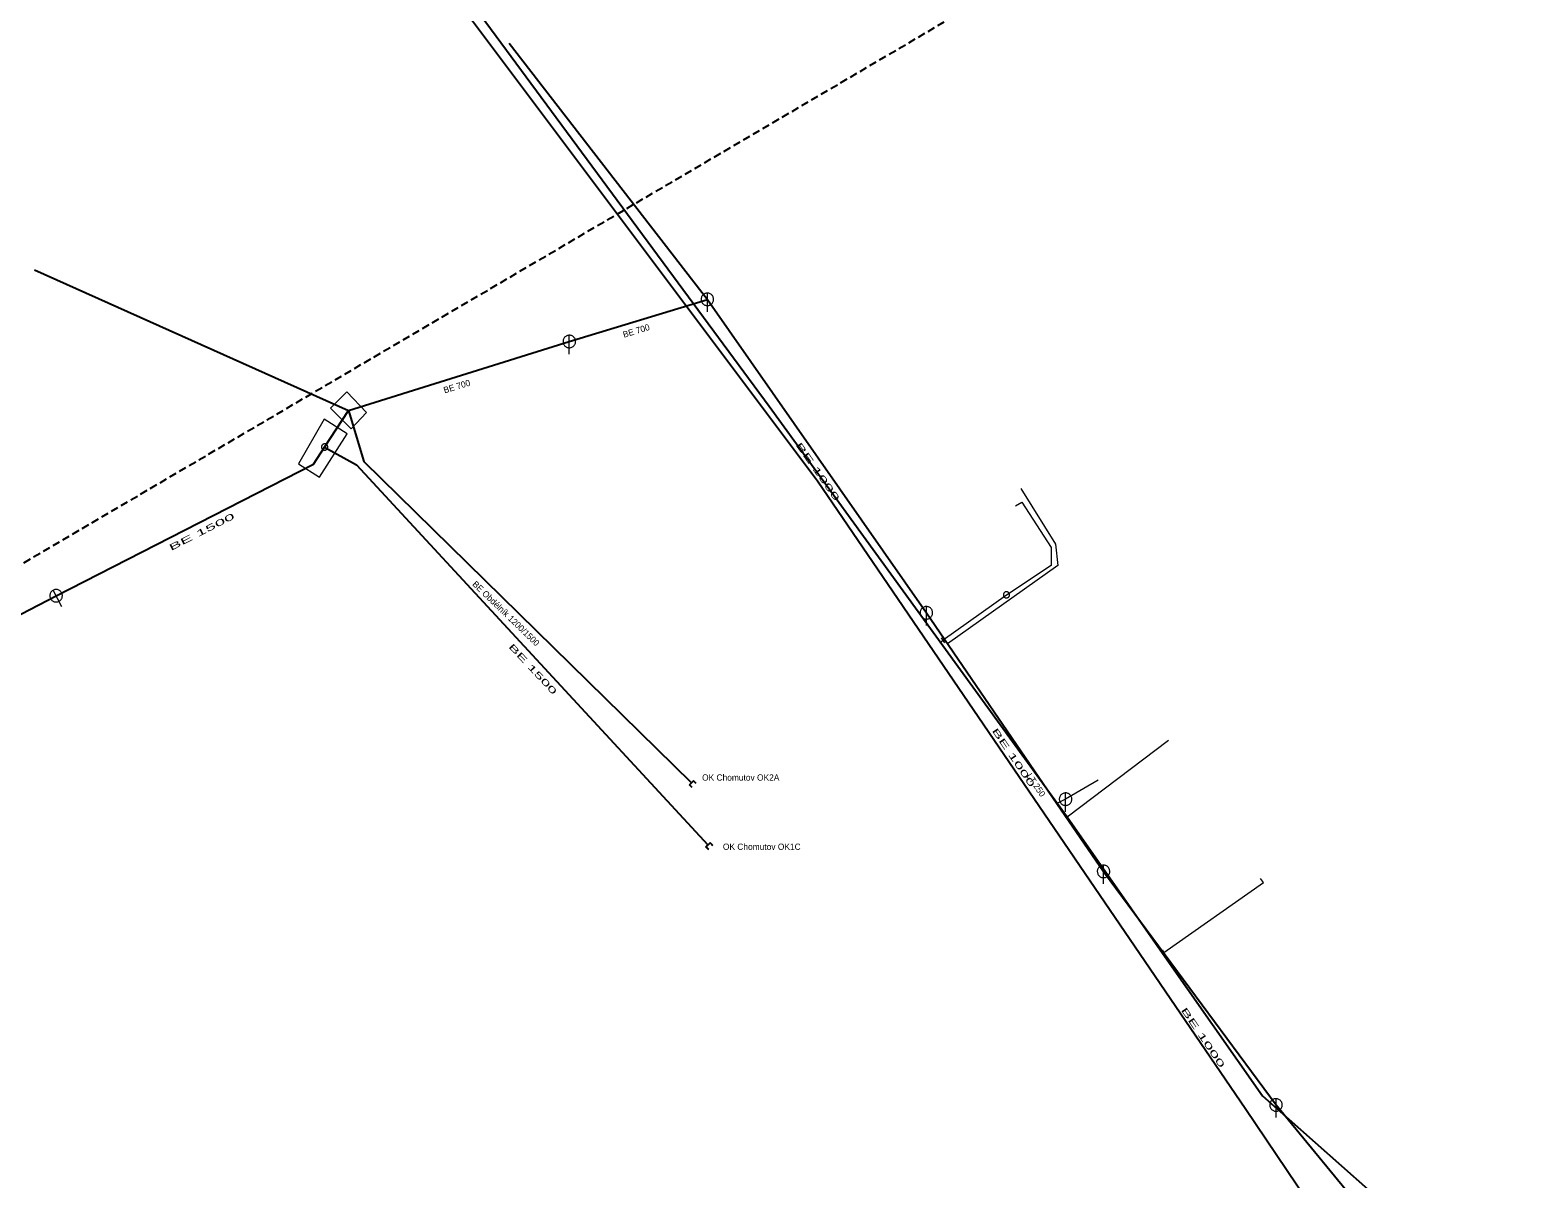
# Model space of a CAD drawing. Extents: x -807203 to -805207, y -993656 to -992505.
# Drawn here: x -806744.2 to -806503.5, y -992783.3 to -992600 of the extents above; entities that cross this region are included whole.
import ezdxf

# ---------------------------------------------------------------- set-up
doc = ezdxf.new("R2010")
doc.units = 0
doc.header["$LTSCALE"] = 0.4
doc.linetypes.add('MEDIUM_DASHED', pattern=[4.5, 3, -1.5])
for name, color, linetype, lineweight in [('1', 7, 'Continuous', 13), ('11', 7, 'Continuous', 13), ('13', 7, 'Continuous', 13), ('14', 7, 'Continuous', 25), ('17', 7, 'Continuous', 25), ('22', 7, 'Continuous', 13), ('23', 7, 'Continuous', 13), ('29', 7, 'Continuous', 13), ('31', 7, 'Continuous', 13), ('34', 7, 'Continuous', 13), ('63', 7, 'MEDIUM_DASHED', 25)]:
    doc.layers.add(name, color=color, linetype=linetype, lineweight=lineweight)

msp = doc.modelspace()

# ---------------------------------------------------------------- linework, layer by layer
at = {"layer": '1'}
for points in [[(-806693.63, -992657.714), (-806696.28, -992660.291), (-806692.966, -992663.625), (-806690.539, -992660.993)], [(-806697.274, -992662.058), (-806701.357, -992669.204), (-806698.039, -992671.347), (-806693.599, -992664.406)]]:
    msp.add_lwpolyline(points, close=True, dxfattribs=at)
at = {"layer": '11'}
for p, q in [((-806573.713, -992719.711), (-806578.93, -992722.73)), ((-806578.93, -992722.73), (-806580.31, -992723.399))]:
    msp.add_line(p, q, dxfattribs=at)
msp.add_lwpolyline([(-806586.063, -992673.109), (-806580.563, -992682.012), (-806580.166, -992685.451), (-806597.76, -992697.928)], dxfattribs=at)
at = {"layer": '13'}
for p, q in [((-806588.368, -992690.147), (-806598.47, -992697.356)), ((-806598.914, -992697.673), (-806598.47, -992697.356)), ((-806578.693, -992725.553), (-806562.513, -992713.331))]:
    msp.add_line(p, q, dxfattribs=at)
for points in [[(-806586.913, -992675.926), (-806585.921, -992675.331), (-806581.224, -992682.541), (-806581.224, -992685.451), (-806588.368, -992690.147)], [(-806563.258, -992747.217), (-806547.336, -992736.038), (-806547.826, -992735.393)]]:
    msp.add_lwpolyline(points, dxfattribs=at)
at = {"layer": '14'}
for p, q in [((-806667.734, -992602.07), (-806636.101, -992642.942)), ((-806743.532, -992638.21), (-806693.41, -992660.67)), ((-806636.101, -992642.942), (-806601.151, -992692.978)), ((-806572.87, -992734.26), (-806545.34, -992771.539)), ((-806545.34, -992771.539), (-806510.489, -992813.739))]:
    msp.add_line(p, q, dxfattribs=at)
at = {"layer": '14', "lineweight": 13}
msp.add_line((-806563.455, -992747.297), (-806563.258, -992747.217), dxfattribs=at)
at = {"layer": '14'}
for points in [[(-806693.41, -992660.67), (-806658.14, -992649.67), (-806636.101, -992642.942)], [(-806784.8, -992713.495), (-806740.059, -992690.25), (-806698.98, -992669.26), (-806697.199, -992666.514), (-806693.41, -992660.67)], [(-806693.41, -992660.67), (-806690.953, -992668.827), (-806638.67, -992720.07)], [(-806697.199, -992666.514), (-806692.136, -992669.339), (-806636.03, -992730)], [(-806601.151, -992692.978), (-806580.31, -992723.399), (-806572.87, -992734.26)]]:
    msp.add_lwpolyline(points, dxfattribs=at)
at = {"layer": '17'}
for points in [[(-806778.418, -992505.129), (-806735.947, -992534.177), (-806710.556, -992555.706), (-806685.234, -992582.874), (-806618.534, -992671.901), (-806550.144, -992772.21), (-806538.741, -992789.206), (-806527.647, -992801.493), (-806521.969, -992806.479)], [(-806713.738, -992548.818), (-806700.103, -992562.285), (-806693.842, -992569.743), (-806679.548, -992587.69), (-806626.239, -992660.002), (-806578.693, -992725.552), (-806563.455, -992747.297), (-806547.484, -992770.088), (-806530.704, -992784.989), (-806525.097, -992790.538), (-806497.604, -992819.259), (-806477.405, -992839.403), (-806476.543, -992840.262)]]:
    msp.add_lwpolyline(points, dxfattribs=at)
at = {"layer": '22'}
for p, q in [((-806636.101, -992644.942), (-806636.1, -992641.942)), ((-806658.14, -992651.67), (-806658.139, -992648.67)), ((-806739.143, -992692.028), (-806740.516, -992689.361)), ((-806601.151, -992694.978), (-806601.15, -992691.978)), ((-806578.93, -992724.73), (-806578.929, -992721.73)), ((-806572.87, -992736.26), (-806572.869, -992733.26)), ((-806545.34, -992773.539), (-806545.339, -992770.539))]:
    msp.add_line(p, q, dxfattribs=at)
for points in [[(-806635.101, -992642.942), (-806635.106, -992642.833), (-806635.124, -992642.725), (-806635.154, -992642.619), (-806635.194, -992642.518), (-806635.246, -992642.421), (-806635.308, -992642.331), (-806635.38, -992642.248), (-806635.46, -992642.174), (-806635.548, -992642.108), (-806635.642, -992642.053), (-806635.742, -992642.008), (-806635.847, -992641.975), (-806635.954, -992641.953), (-806636.063, -992641.943), (-806636.173, -992641.945), (-806636.281, -992641.959), (-806636.388, -992641.984), (-806636.491, -992642.021), (-806636.589, -992642.07), (-806636.681, -992642.128), (-806636.767, -992642.197), (-806636.844, -992642.274), (-806636.913, -992642.36), (-806636.972, -992642.452), (-806637.02, -992642.55), (-806637.057, -992642.653), (-806637.083, -992642.76), (-806637.097, -992642.868), (-806637.1, -992642.978), (-806637.09, -992643.087), (-806637.069, -992643.194), (-806637.035, -992643.298), (-806636.991, -992643.398), (-806636.936, -992643.493), (-806636.87, -992643.581), (-806636.796, -992643.661), (-806636.713, -992643.733), (-806636.623, -992643.795), (-806636.527, -992643.847), (-806636.425, -992643.888), (-806636.32, -992643.918), (-806636.212, -992643.936), (-806636.102, -992643.942), (-806635.993, -992643.936), (-806635.885, -992643.918), (-806635.78, -992643.889), (-806635.678, -992643.848), (-806635.581, -992643.796), (-806635.491, -992643.734), (-806635.408, -992643.663), (-806635.333, -992643.583), (-806635.268, -992643.495), (-806635.212, -992643.401), (-806635.168, -992643.301), (-806635.134, -992643.197), (-806635.112, -992643.089), (-806635.102, -992642.98)], [(-806657.14, -992649.67), (-806657.145, -992649.561), (-806657.163, -992649.453), (-806657.193, -992649.347), (-806657.233, -992649.246), (-806657.285, -992649.149), (-806657.347, -992649.059), (-806657.419, -992648.976), (-806657.499, -992648.902), (-806657.587, -992648.836), (-806657.681, -992648.781), (-806657.781, -992648.736), (-806657.886, -992648.703), (-806657.993, -992648.681), (-806658.102, -992648.671), (-806658.212, -992648.673), (-806658.32, -992648.687), (-806658.427, -992648.712), (-806658.53, -992648.749), (-806658.628, -992648.798), (-806658.72, -992648.856), (-806658.806, -992648.925), (-806658.883, -992649.002), (-806658.952, -992649.088), (-806659.011, -992649.18), (-806659.059, -992649.278), (-806659.096, -992649.381), (-806659.122, -992649.488), (-806659.136, -992649.596), (-806659.139, -992649.706), (-806659.129, -992649.815), (-806659.108, -992649.922), (-806659.074, -992650.026), (-806659.03, -992650.126), (-806658.975, -992650.221), (-806658.909, -992650.309), (-806658.835, -992650.389), (-806658.752, -992650.461), (-806658.662, -992650.523), (-806658.566, -992650.575), (-806658.464, -992650.616), (-806658.359, -992650.646), (-806658.251, -992650.664), (-806658.141, -992650.67), (-806658.032, -992650.664), (-806657.924, -992650.646), (-806657.819, -992650.617), (-806657.717, -992650.576), (-806657.62, -992650.524), (-806657.53, -992650.462), (-806657.447, -992650.391), (-806657.372, -992650.311), (-806657.307, -992650.223), (-806657.251, -992650.129), (-806657.207, -992650.029), (-806657.173, -992649.925), (-806657.151, -992649.817), (-806657.141, -992649.708)], [(-806739.169, -992689.792), (-806739.224, -992689.698), (-806739.29, -992689.61), (-806739.365, -992689.53), (-806739.447, -992689.458), (-806739.538, -992689.396), (-806739.634, -992689.344), (-806739.736, -992689.303), (-806739.841, -992689.274), (-806739.949, -992689.256), (-806740.058, -992689.25), (-806740.168, -992689.256), (-806740.276, -992689.274), (-806740.381, -992689.304), (-806740.483, -992689.345), (-806740.58, -992689.397), (-806740.669, -992689.459), (-806740.753, -992689.53), (-806740.828, -992689.61), (-806740.892, -992689.699), (-806740.947, -992689.792), (-806740.992, -992689.893), (-806741.026, -992689.997), (-806741.048, -992690.105), (-806741.058, -992690.214), (-806741.056, -992690.323), (-806741.041, -992690.431), (-806741.016, -992690.538), (-806740.979, -992690.641), (-806740.93, -992690.739), (-806740.871, -992690.832), (-806740.803, -992690.917), (-806740.726, -992690.994), (-806740.641, -992691.063), (-806740.548, -992691.122), (-806740.449, -992691.17), (-806740.347, -992691.207), (-806740.24, -992691.233), (-806740.132, -992691.247), (-806740.023, -992691.25), (-806739.913, -992691.239), (-806739.806, -992691.218), (-806739.702, -992691.184), (-806739.601, -992691.139), (-806739.507, -992691.084), (-806739.419, -992691.019), (-806739.339, -992690.945), (-806739.267, -992690.862), (-806739.205, -992690.771), (-806739.153, -992690.675), (-806739.112, -992690.574), (-806739.082, -992690.468), (-806739.065, -992690.36), (-806739.058, -992690.251), (-806739.064, -992690.142), (-806739.082, -992690.034), (-806739.112, -992689.928), (-806739.153, -992689.826)], [(-806600.151, -992692.978), (-806600.156, -992692.869), (-806600.174, -992692.761), (-806600.204, -992692.655), (-806600.244, -992692.554), (-806600.296, -992692.457), (-806600.358, -992692.367), (-806600.43, -992692.284), (-806600.51, -992692.21), (-806600.598, -992692.144), (-806600.692, -992692.089), (-806600.792, -992692.044), (-806600.897, -992692.011), (-806601.004, -992691.989), (-806601.113, -992691.979), (-806601.223, -992691.981), (-806601.331, -992691.995), (-806601.438, -992692.02), (-806601.541, -992692.057), (-806601.639, -992692.106), (-806601.731, -992692.164), (-806601.817, -992692.233), (-806601.894, -992692.31), (-806601.963, -992692.396), (-806602.022, -992692.488), (-806602.07, -992692.586), (-806602.107, -992692.689), (-806602.133, -992692.796), (-806602.147, -992692.904), (-806602.15, -992693.014), (-806602.14, -992693.123), (-806602.119, -992693.23), (-806602.085, -992693.334), (-806602.041, -992693.434), (-806601.986, -992693.529), (-806601.92, -992693.617), (-806601.846, -992693.697), (-806601.763, -992693.769), (-806601.673, -992693.831), (-806601.577, -992693.883), (-806601.475, -992693.924), (-806601.37, -992693.954), (-806601.262, -992693.972), (-806601.152, -992693.978), (-806601.043, -992693.972), (-806600.935, -992693.954), (-806600.83, -992693.925), (-806600.728, -992693.884), (-806600.631, -992693.832), (-806600.541, -992693.77), (-806600.458, -992693.699), (-806600.383, -992693.619), (-806600.318, -992693.531), (-806600.262, -992693.437), (-806600.218, -992693.337), (-806600.184, -992693.233), (-806600.162, -992693.125), (-806600.152, -992693.016)], [(-806577.93, -992722.73), (-806577.935, -992722.621), (-806577.953, -992722.513), (-806577.983, -992722.407), (-806578.023, -992722.306), (-806578.075, -992722.209), (-806578.137, -992722.119), (-806578.209, -992722.036), (-806578.289, -992721.962), (-806578.377, -992721.896), (-806578.471, -992721.841), (-806578.571, -992721.796), (-806578.676, -992721.763), (-806578.783, -992721.741), (-806578.892, -992721.731), (-806579.002, -992721.733), (-806579.11, -992721.747), (-806579.217, -992721.772), (-806579.32, -992721.809), (-806579.418, -992721.858), (-806579.51, -992721.916), (-806579.596, -992721.985), (-806579.673, -992722.062), (-806579.742, -992722.148), (-806579.801, -992722.24), (-806579.849, -992722.338), (-806579.886, -992722.441), (-806579.912, -992722.548), (-806579.926, -992722.656), (-806579.929, -992722.766), (-806579.919, -992722.875), (-806579.898, -992722.982), (-806579.864, -992723.086), (-806579.82, -992723.186), (-806579.765, -992723.281), (-806579.699, -992723.369), (-806579.625, -992723.449), (-806579.542, -992723.521), (-806579.452, -992723.583), (-806579.356, -992723.635), (-806579.254, -992723.676), (-806579.149, -992723.706), (-806579.041, -992723.724), (-806578.931, -992723.73), (-806578.822, -992723.724), (-806578.714, -992723.706), (-806578.609, -992723.677), (-806578.507, -992723.636), (-806578.41, -992723.584), (-806578.32, -992723.522), (-806578.237, -992723.451), (-806578.162, -992723.371), (-806578.097, -992723.283), (-806578.041, -992723.189), (-806577.997, -992723.089), (-806577.963, -992722.985), (-806577.941, -992722.877), (-806577.931, -992722.768)], [(-806571.87, -992734.26), (-806571.875, -992734.151), (-806571.893, -992734.043), (-806571.923, -992733.937), (-806571.963, -992733.836), (-806572.015, -992733.739), (-806572.077, -992733.649), (-806572.149, -992733.566), (-806572.229, -992733.492), (-806572.317, -992733.426), (-806572.411, -992733.371), (-806572.511, -992733.326), (-806572.616, -992733.293), (-806572.723, -992733.271), (-806572.832, -992733.261), (-806572.942, -992733.263), (-806573.05, -992733.277), (-806573.157, -992733.302), (-806573.26, -992733.339), (-806573.358, -992733.388), (-806573.45, -992733.446), (-806573.536, -992733.515), (-806573.613, -992733.592), (-806573.682, -992733.678), (-806573.741, -992733.77), (-806573.789, -992733.868), (-806573.826, -992733.971), (-806573.852, -992734.078), (-806573.866, -992734.186), (-806573.869, -992734.296), (-806573.859, -992734.405), (-806573.838, -992734.512), (-806573.804, -992734.616), (-806573.76, -992734.716), (-806573.705, -992734.811), (-806573.639, -992734.899), (-806573.565, -992734.979), (-806573.482, -992735.051), (-806573.392, -992735.113), (-806573.296, -992735.165), (-806573.194, -992735.206), (-806573.089, -992735.236), (-806572.981, -992735.254), (-806572.871, -992735.26), (-806572.762, -992735.254), (-806572.654, -992735.236), (-806572.549, -992735.207), (-806572.447, -992735.166), (-806572.35, -992735.114), (-806572.26, -992735.052), (-806572.177, -992734.981), (-806572.102, -992734.901), (-806572.037, -992734.813), (-806571.981, -992734.719), (-806571.937, -992734.619), (-806571.903, -992734.515), (-806571.881, -992734.407), (-806571.871, -992734.298)], [(-806544.34, -992771.539), (-806544.345, -992771.43), (-806544.363, -992771.322), (-806544.393, -992771.216), (-806544.433, -992771.115), (-806544.485, -992771.018), (-806544.547, -992770.928), (-806544.619, -992770.845), (-806544.699, -992770.771), (-806544.787, -992770.705), (-806544.881, -992770.65), (-806544.981, -992770.605), (-806545.086, -992770.572), (-806545.193, -992770.55), (-806545.302, -992770.54), (-806545.412, -992770.542), (-806545.52, -992770.556), (-806545.627, -992770.581), (-806545.73, -992770.618), (-806545.828, -992770.667), (-806545.92, -992770.725), (-806546.006, -992770.794), (-806546.083, -992770.871), (-806546.152, -992770.957), (-806546.211, -992771.049), (-806546.259, -992771.147), (-806546.296, -992771.25), (-806546.322, -992771.357), (-806546.336, -992771.465), (-806546.339, -992771.575), (-806546.329, -992771.684), (-806546.308, -992771.791), (-806546.274, -992771.895), (-806546.23, -992771.995), (-806546.175, -992772.09), (-806546.109, -992772.178), (-806546.035, -992772.258), (-806545.952, -992772.33), (-806545.862, -992772.392), (-806545.766, -992772.444), (-806545.664, -992772.485), (-806545.559, -992772.515), (-806545.451, -992772.533), (-806545.341, -992772.539), (-806545.232, -992772.533), (-806545.124, -992772.515), (-806545.019, -992772.486), (-806544.917, -992772.445), (-806544.82, -992772.393), (-806544.73, -992772.331), (-806544.647, -992772.26), (-806544.572, -992772.18), (-806544.507, -992772.092), (-806544.451, -992771.998), (-806544.407, -992771.898), (-806544.373, -992771.794), (-806544.351, -992771.686), (-806544.341, -992771.577)]]:
    msp.add_lwpolyline(points, close=True, dxfattribs=at)
at = {"layer": '23'}
for points in [[(-806588.343, -992689.615), (-806588.395, -992689.616), (-806588.447, -992689.623), (-806588.498, -992689.633), (-806588.548, -992689.652), (-806588.594, -992689.674), (-806588.639, -992689.7), (-806588.681, -992689.732), (-806588.72, -992689.767), (-806588.755, -992689.807), (-806588.784, -992689.85), (-806588.81, -992689.896), (-806588.83, -992689.943), (-806588.845, -992689.994), (-806588.856, -992690.044), (-806588.86, -992690.096), (-806588.86, -992690.15), (-806588.853, -992690.202), (-806588.841, -992690.253), (-806588.823, -992690.302), (-806588.802, -992690.349), (-806588.776, -992690.394), (-806588.744, -992690.437), (-806588.708, -992690.475), (-806588.669, -992690.508), (-806588.626, -992690.538), (-806588.58, -992690.564), (-806588.531, -992690.584), (-806588.482, -992690.599), (-806588.431, -992690.609), (-806588.379, -992690.614), (-806588.326, -992690.613), (-806588.274, -992690.607), (-806588.222, -992690.595), (-806588.173, -992690.578), (-806588.127, -992690.556), (-806588.082, -992690.53), (-806588.039, -992690.497), (-806588.001, -992690.463), (-806587.966, -992690.422)], [(-806587.966, -992690.422), (-806587.937, -992690.381), (-806587.911, -992690.335), (-806587.891, -992690.285), (-806587.876, -992690.236), (-806587.866, -992690.183), (-806587.86, -992690.132), (-806587.862, -992690.08), (-806587.869, -992690.028), (-806587.88, -992689.978), (-806587.897, -992689.928), (-806587.92, -992689.88), (-806587.946, -992689.835), (-806587.977, -992689.794), (-806588.013, -992689.755), (-806588.053, -992689.72), (-806588.095, -992689.69), (-806588.141, -992689.667), (-806588.189, -992689.646), (-806588.239, -992689.63), (-806588.291, -992689.62), (-806588.343, -992689.615), (-806588.395, -992689.616), (-806588.447, -992689.623), (-806588.498, -992689.633), (-806588.548, -992689.652), (-806588.594, -992689.674), (-806588.639, -992689.7), (-806588.681, -992689.732), (-806588.72, -992689.767), (-806588.755, -992689.807), (-806588.784, -992689.85), (-806588.81, -992689.896), (-806588.83, -992689.943), (-806588.845, -992689.994), (-806588.856, -992690.044), (-806588.86, -992690.096), (-806588.86, -992690.15), (-806588.853, -992690.202), (-806588.841, -992690.253)], [(-806588.841, -992690.253), (-806588.823, -992690.302), (-806588.802, -992690.349), (-806588.776, -992690.394)], [(-806588.776, -992690.394), (-806588.744, -992690.437), (-806588.708, -992690.475), (-806588.669, -992690.508), (-806588.626, -992690.538), (-806588.58, -992690.564), (-806588.531, -992690.584), (-806588.482, -992690.599), (-806588.431, -992690.609), (-806588.379, -992690.614), (-806588.326, -992690.613), (-806588.274, -992690.607), (-806588.222, -992690.595), (-806588.173, -992690.578), (-806588.127, -992690.556), (-806588.082, -992690.53), (-806588.039, -992690.497), (-806588.001, -992690.463), (-806587.966, -992690.422), (-806587.937, -992690.381), (-806587.911, -992690.335), (-806587.891, -992690.285), (-806587.876, -992690.236), (-806587.866, -992690.183), (-806587.86, -992690.132), (-806587.862, -992690.08), (-806587.869, -992690.028), (-806587.88, -992689.978), (-806587.897, -992689.928), (-806587.92, -992689.88), (-806587.946, -992689.835), (-806587.977, -992689.794), (-806588.013, -992689.755), (-806588.053, -992689.72), (-806588.095, -992689.69), (-806588.141, -992689.667), (-806588.189, -992689.646), (-806588.239, -992689.63), (-806588.291, -992689.62), (-806588.343, -992689.615)]]:
    msp.add_lwpolyline(points, dxfattribs=at)
at = {"layer": '29'}
for points in [[(-806637.88, -992720.172), (-806638.312, -992719.725), (-806639.026, -992720.414), (-806638.593, -992720.862)], [(-806638.531, -992720.801), (-806638.903, -992720.417), (-806638.315, -992719.848), (-806637.943, -992720.233)], [(-806635.24, -992730.096), (-806635.675, -992729.653), (-806636.383, -992730.347), (-806635.947, -992730.791)], [(-806635.885, -992730.73), (-806636.26, -992730.348), (-806635.676, -992729.776), (-806635.302, -992730.158)]]:
    msp.add_lwpolyline(points, dxfattribs=at)
at = {"layer": '31'}
for points in [[(-806696.926, -992666.094), (-806696.972, -992666.068), (-806697.02, -992666.047), (-806697.069, -992666.031), (-806697.12, -992666.02), (-806697.173, -992666.014), (-806697.225, -992666.015), (-806697.277, -992666.02), (-806697.328, -992666.031), (-806697.378, -992666.047), (-806697.426, -992666.068), (-806697.472, -992666.095), (-806697.513, -992666.126), (-806697.552, -992666.16), (-806697.587, -992666.199), (-806697.618, -992666.241), (-806697.644, -992666.287), (-806697.665, -992666.335), (-806697.681, -992666.385), (-806697.692, -992666.435), (-806697.698, -992666.488), (-806697.697, -992666.54), (-806697.692, -992666.593), (-806697.681, -992666.644), (-806697.666, -992666.693), (-806697.644, -992666.741), (-806697.617, -992666.787), (-806697.587, -992666.829), (-806697.552, -992666.867), (-806697.513, -992666.902), (-806697.471, -992666.933), (-806697.425, -992666.959), (-806697.377, -992666.98), (-806697.327, -992666.997), (-806697.277, -992667.007), (-806697.224, -992667.013), (-806697.172, -992667.013), (-806697.12, -992667.008), (-806697.069, -992666.997), (-806697.019, -992666.981), (-806696.971, -992666.959), (-806696.925, -992666.932), (-806696.883, -992666.903), (-806696.845, -992666.867), (-806696.81, -992666.828), (-806696.779, -992666.786), (-806696.753, -992666.74), (-806696.732, -992666.692), (-806696.715, -992666.643), (-806696.705, -992666.592), (-806696.699, -992666.539), (-806696.699, -992666.487), (-806696.705, -992666.436), (-806696.716, -992666.384), (-806696.732, -992666.334), (-806696.753, -992666.286), (-806696.78, -992666.24), (-806696.81, -992666.199), (-806696.845, -992666.16), (-806696.884, -992666.125)], [(-806697.154, -992666.445), (-806697.161, -992666.44), (-806697.169, -992666.437), (-806697.177, -992666.434), (-806697.185, -992666.433), (-806697.194, -992666.432), (-806697.203, -992666.432), (-806697.211, -992666.432), (-806697.22, -992666.434), (-806697.228, -992666.437), (-806697.236, -992666.44), (-806697.243, -992666.445), (-806697.25, -992666.45), (-806697.256, -992666.456), (-806697.262, -992666.461), (-806697.267, -992666.469), (-806697.272, -992666.476), (-806697.275, -992666.484), (-806697.278, -992666.492), (-806697.279, -992666.5), (-806697.28, -992666.509), (-806697.28, -992666.518), (-806697.28, -992666.526), (-806697.278, -992666.535), (-806697.275, -992666.544), (-806697.272, -992666.551), (-806697.267, -992666.558), (-806697.262, -992666.565), (-806697.256, -992666.571), (-806697.251, -992666.577), (-806697.243, -992666.582), (-806697.236, -992666.587), (-806697.228, -992666.59), (-806697.22, -992666.593), (-806697.212, -992666.594), (-806697.203, -992666.595), (-806697.195, -992666.596), (-806697.186, -992666.595), (-806697.177, -992666.593), (-806697.168, -992666.59), (-806697.161, -992666.587), (-806697.154, -992666.582), (-806697.147, -992666.577), (-806697.141, -992666.571), (-806697.135, -992666.566), (-806697.13, -992666.558), (-806697.125, -992666.551), (-806697.122, -992666.543), (-806697.119, -992666.535), (-806697.118, -992666.527), (-806697.117, -992666.518), (-806697.116, -992666.51), (-806697.117, -992666.501), (-806697.119, -992666.492), (-806697.122, -992666.484), (-806697.125, -992666.476), (-806697.13, -992666.469), (-806697.135, -992666.462), (-806697.141, -992666.456), (-806697.146, -992666.45)]]:
    msp.add_lwpolyline(points, close=True, dxfattribs=at)
at = {"layer": '34'}
for p, q in [((-806598.179, -992697.762), (-806598.76, -992696.948)), ((-806563.446, -992746.753), (-806563.07, -992747.68))]:
    msp.add_line(p, q, dxfattribs=at)
at = {"layer": '63'}
msp.add_lwpolyline([(-807189.02, -992945.815), (-806576.348, -992585.749), (-806576.348, -992585.749), (-805244.939, -992598.309), (-805244.939, -992598.309), (-805207.257, -992947.211), (-805207.257, -992947.211), (-805210.049, -993545.926), (-805210.049, -993545.926), (-805797.599, -993596.168), (-805797.599, -993596.168), (-807062.019, -993558.487), (-807062.019, -993558.487)], close=True, dxfattribs=at)

# ---------------------------------------------------------------- texts
at = {"layer": '1'}
for s, rotation, p in [('BE 700', 17, (-806649.41, -992649.08)), ('BE 700', 17, (-806678.047, -992657.957)), ('BE Obdélník 1200/1500 ', 316, (-806673.699, -992688.516)), ('LT 250', 304, (-806585.214, -992719.021))]:
    msp.add_text(s, height=1, rotation=rotation, dxfattribs=at).set_placement(p)
for s, rotation, width, p in [('BE 1000 ', 305, 2.15, (-806622.048, -992666.199)), ('BE 1500 ', 27, 2.25, (-806721.733, -992683.114)), ('BE 1500 ', 313, 2.05, (-806667.916, -992698.448)), ('BE 1000 ', 304, 2.15, (-806590.742, -992711.783)), ('BE 1000 ', 304, 2.2, (-806560.56, -992756.375))]:
    msp.add_text(s, height=1, rotation=rotation, dxfattribs=dict(at, width=width)).set_placement(p)
for s, p in [('OK Chomutov OK2A', (-806636.949, -992719.771)), ('OK Chomutov OK1C', (-806633.626, -992730.819))]:
    msp.add_text(s, height=1, dxfattribs=at).set_placement(p)

doc.saveas('drawing.dxf')
